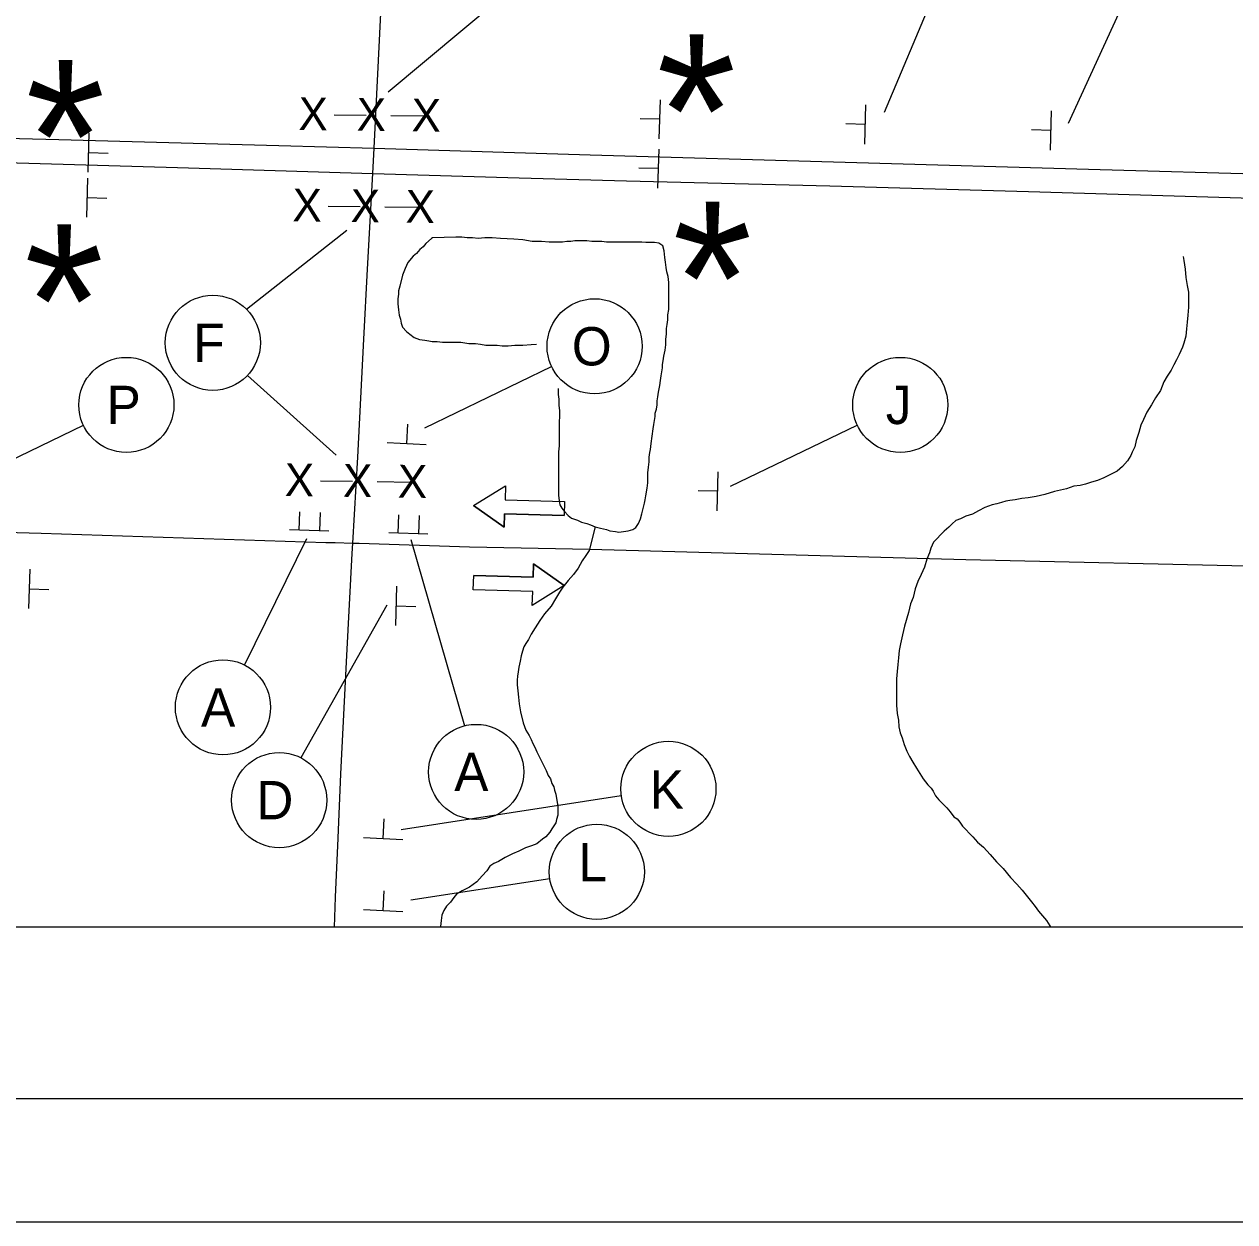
# Model space of a CAD drawing. Extents: x 1 to 1971, y -2 to 1107.
# Drawn here: x 1655.229 to 1660.159, y 1084.601 to 1089.477 of the extents above; entities that cross this region are included whole.
import ezdxf

# ---------------------------------------------------------------- set-up
doc = ezdxf.new("R2010")
doc.units = 0
for name, color, linetype in [('GM_X_County_Road', 7, 'Continuous'), ('GM_X_Minor_River', 7, 'Continuous'), ('GM_X_State_Route', 7, 'Continuous'), ('GM_X_Township_Road', 7, 'Continuous'), ('SH_Border', 7, 'Continuous'), ('SH_Cut_Line', 7, 'Continuous'), ('SH_Data', 7, 'Continuous'), ('SH_Text', 7, 'Continuous'), ('SN_P_Signs', 7, 'Continuous'), ('SN_X_Public', 7, 'Continuous')]:
    doc.layers.add(name, color=color, linetype=linetype)

msp = doc.modelspace()

# ---------------------------------------------------------------- linework, layer by layer
at = {"layer": 'GM_X_County_Road'}
for points in [[(1656.6538, 1088.9713), (1656.6824, 1089.549), (1656.7502, 1090.7723), (1656.779, 1091.2527), (1656.8004, 1091.6678), (1656.8346, 1092.2577), (1656.8383, 1092.3049), (1656.8451, 1092.3768), (1656.8483, 1092.4109)], [(1656.6538, 1088.9713), (1656.6824, 1089.549), (1656.7502, 1090.7723), (1656.779, 1091.2527), (1656.8004, 1091.6678), (1656.8346, 1092.2577), (1656.8383, 1092.3049), (1656.8451, 1092.3768), (1656.8483, 1092.4109)], [(1656.6489, 1088.8688), (1656.6538, 1088.9713)], [(1656.6489, 1088.8688), (1656.6538, 1088.9713)], [(1656.5672, 1087.3642), (1656.5873, 1087.7139), (1656.6125, 1088.1945), (1656.6271, 1088.4787), (1656.6489, 1088.8688)], [(1656.5672, 1087.3642), (1656.5873, 1087.7139), (1656.6125, 1088.1945), (1656.6271, 1088.4787), (1656.6489, 1088.8688)], [(1653.1763, 1087.4595), (1653.5925, 1087.4528), (1654.5111, 1087.4263), (1655.2983, 1087.4042), (1656.4573, 1087.3668), (1656.495, 1087.3659), (1656.5672, 1087.3642)], [(1653.1763, 1087.4595), (1653.5925, 1087.4528), (1654.5111, 1087.4263), (1655.2983, 1087.4042), (1656.4573, 1087.3668), (1656.495, 1087.3659), (1656.5672, 1087.3642)], [(1656.5672, 1087.3642), (1656.5934, 1087.3633), (1657.0425, 1087.3482), (1657.533, 1087.3387), (1659.0643, 1087.2977), (1660.2675, 1087.2696), (1661.405, 1087.2377), (1662.6955, 1087.1976), (1663.5705, 1087.1736), (1663.7236, 1087.1696)], [(1656.5672, 1087.3642), (1656.5934, 1087.3633), (1657.0425, 1087.3482), (1657.533, 1087.3387), (1659.0643, 1087.2977), (1660.2675, 1087.2696), (1661.405, 1087.2377), (1662.6955, 1087.1976), (1663.5705, 1087.1736), (1663.7236, 1087.1696)]]:
    msp.add_lwpolyline(points, dxfattribs=at)
at = {"layer": 'GM_X_Minor_River'}
for points in [[(1656.8922, 1088.6067), (1656.8884, 1088.6046), (1656.8642, 1088.5832), (1656.8535, 1088.5699), (1656.8401, 1088.5592), (1656.8267, 1088.5432), (1656.8133, 1088.5326), (1656.7918, 1088.5059), (1656.7811, 1088.4818), (1656.7757, 1088.4685), (1656.7703, 1088.4551), (1656.7595, 1088.4097), (1656.7541, 1088.391), (1656.7541, 1088.3776), (1656.7513, 1088.3589), (1656.7513, 1088.3375), (1656.7539, 1088.3134), (1656.7565, 1088.292), (1656.7619, 1088.2759), (1656.7645, 1088.2598), (1656.7698, 1088.2437), (1656.7858, 1088.225), (1656.7992, 1088.2142), (1656.8179, 1088.2008), (1656.8393, 1088.1927), (1656.8607, 1088.19), (1656.8767, 1088.1872), (1656.8901, 1088.1845), (1656.9115, 1088.1845), (1656.9329, 1088.1817), (1656.957, 1088.1816), (1656.9811, 1088.1815), (1657.0078, 1088.1815), (1657.0399, 1088.176), (1657.0667, 1088.1759), (1657.0881, 1088.1732), (1657.1095, 1088.1704), (1657.1335, 1088.1704), (1657.155, 1088.1703), (1657.1763, 1088.1675), (1657.2004, 1088.1675), (1657.2272, 1088.1701), (1657.2593, 1088.1699), (1657.2941, 1088.1725), (1657.3151, 1088.174)], [(1657.7071, 1087.4194), (1657.7205, 1087.4274), (1657.7313, 1087.4434), (1657.7393, 1087.4621), (1657.7447, 1087.4835), (1657.7501, 1087.5049), (1657.7555, 1087.5263), (1657.7582, 1087.5396), (1657.7609, 1087.5557), (1657.7664, 1087.5878), (1657.7691, 1087.6092), (1657.7691, 1087.6279), (1657.7692, 1087.6493), (1657.7719, 1087.6734), (1657.7746, 1087.6948), (1657.7747, 1087.7135), (1657.7774, 1087.7322), (1657.7801, 1087.7456), (1657.7828, 1087.7697), (1657.791, 1087.8285), (1657.7937, 1087.8472), (1657.7964, 1087.8632), (1657.7991, 1087.8793), (1657.7992, 1087.8927), (1657.8045, 1087.9087), (1657.8073, 1087.9274), (1657.8073, 1087.9435), (1657.81, 1087.9595), (1657.8127, 1087.9782), (1657.8181, 1088.005), (1657.8209, 1088.0264), (1657.8236, 1088.0451), (1657.8263, 1088.0611), (1657.829, 1088.0772), (1657.8291, 1088.0906), (1657.8318, 1088.1066), (1657.8345, 1088.1253), (1657.8399, 1088.1494), (1657.8426, 1088.1708), (1657.8427, 1088.1922), (1657.8454, 1088.2162), (1657.8454, 1088.2377), (1657.8482, 1088.2537), (1657.8509, 1088.2724), (1657.8509, 1088.2938), (1657.8537, 1088.3152), (1657.8537, 1088.3366), (1657.8537, 1088.3553), (1657.8538, 1088.3741), (1657.8538, 1088.3928), (1657.8539, 1088.4089), (1657.8539, 1088.4249), (1657.8513, 1088.449), (1657.846, 1088.4677), (1657.8433, 1088.4865), (1657.8407, 1088.5079), (1657.8381, 1088.5266), (1657.8355, 1088.5534), (1657.8302, 1088.5748), (1657.8141, 1088.5856), (1657.7954, 1088.5883), (1657.774, 1088.5884), (1657.7606, 1088.5884), (1657.7446, 1088.5885), (1657.7205, 1088.5885), (1657.7044, 1088.5886), (1657.6911, 1088.5886), (1657.675, 1088.5887), (1657.6616, 1088.5887), (1657.6482, 1088.5888), (1657.6322, 1088.5888), (1657.6161, 1088.5889), (1657.6001, 1088.5889), (1657.5813, 1088.5917), (1657.5626, 1088.5917), (1657.5412, 1088.5918), (1657.5198, 1088.5945), (1657.4904, 1088.5946), (1657.4717, 1088.5947), (1657.4556, 1088.5921), (1657.4395, 1088.5921), (1657.4208, 1088.5895), (1657.3967, 1088.5896), (1657.3673, 1088.5897), (1657.3352, 1088.5924), (1657.2977, 1088.5925), (1657.2603, 1088.598), (1657.2228, 1088.6008), (1657.1693, 1088.6037), (1657.1345, 1088.6065), (1657.1051, 1088.6065), (1657.0783, 1088.604), (1657.0543, 1088.6067), (1657.0329, 1088.6068), (1657.0115, 1088.6095), (1656.9874, 1088.6096), (1656.8922, 1088.6067)], [(1659.9493, 1088.5306), (1659.9519, 1088.5145), (1659.9572, 1088.4797), (1659.9598, 1088.4449), (1659.965, 1088.4128), (1659.9703, 1088.3861), (1659.9703, 1088.3566), (1659.9702, 1088.3245), (1659.9675, 1088.2924), (1659.9647, 1088.263), (1659.962, 1088.2363), (1659.9592, 1088.2068), (1659.9511, 1088.1774), (1659.9457, 1088.1614), (1659.9323, 1088.132), (1659.9215, 1088.1106), (1659.9108, 1088.0893), (1659.9, 1088.0679), (1659.8839, 1088.0439), (1659.8705, 1088.0198), (1659.857, 1087.9851), (1659.8356, 1087.9557), (1659.8194, 1087.9264), (1659.8006, 1087.897), (1659.7872, 1087.8676), (1659.7764, 1087.8435), (1659.7683, 1087.8141), (1659.7576, 1087.7821), (1659.7521, 1087.7553), (1659.7414, 1087.734), (1659.736, 1087.7206), (1659.7226, 1087.6993), (1659.7011, 1087.6752), (1659.6797, 1087.6566), (1659.6529, 1087.6433), (1659.6261, 1087.63), (1659.5993, 1087.6194), (1659.5752, 1087.6114), (1659.5511, 1087.6035), (1659.5297, 1087.5982), (1659.5029, 1087.5956), (1659.4735, 1087.585), (1659.4253, 1087.5745), (1659.3851, 1087.5612), (1659.3503, 1087.5533), (1659.3182, 1087.548), (1659.2914, 1087.5455), (1659.2647, 1087.5402), (1659.2433, 1087.5376), (1659.2272, 1087.5349), (1659.2085, 1087.5297), (1659.1897, 1087.5244), (1659.171, 1087.5191), (1659.1415, 1087.5085), (1659.1147, 1087.4952), (1659.0906, 1087.4819), (1659.0638, 1087.4739), (1659.0424, 1087.4633), (1659.0237, 1087.4553), (1659.0076, 1087.442), (1658.9942, 1087.4287), (1658.9754, 1087.4127), (1658.9325, 1087.3673), (1658.9217, 1087.3433), (1658.9163, 1087.3246), (1658.9056, 1087.2979), (1658.8948, 1087.2658), (1658.8813, 1087.2364), (1658.8679, 1087.207), (1658.8571, 1087.1776), (1658.849, 1087.1429), (1658.8383, 1087.1161), (1658.8301, 1087.0814), (1658.814, 1087.0253), (1658.8059, 1086.9905), (1658.7977, 1086.9531), (1658.7923, 1086.9263), (1658.7896, 1086.8969), (1658.7868, 1086.8702), (1658.7841, 1086.8407), (1658.7814, 1086.8113), (1658.7813, 1086.7739), (1658.7812, 1086.7391), (1658.7811, 1086.7043), (1658.7837, 1086.6695), (1658.789, 1086.6427), (1658.7916, 1086.616), (1658.7969, 1086.5919), (1658.8049, 1086.5705), (1658.8129, 1086.5437), (1658.8235, 1086.5169), (1658.8341, 1086.4955), (1658.8475, 1086.4713), (1658.8635, 1086.4472), (1658.8768, 1086.4257), (1658.8901, 1086.4043), (1658.9088, 1086.3802), (1658.9222, 1086.3667), (1658.9302, 1086.3533), (1658.9408, 1086.3346), (1658.9542, 1086.3185)], [(1657.4034, 1087.9934), (1657.4034, 1087.9822), (1657.4033, 1087.9688), (1657.406, 1087.9501), (1657.4059, 1087.926), (1657.4085, 1087.9019), (1657.4085, 1087.8779), (1657.4084, 1087.8591), (1657.4084, 1087.8431), (1657.4083, 1087.8217), (1657.4083, 1087.8029), (1657.4083, 1087.7842), (1657.4082, 1087.7601), (1657.4055, 1087.7361), (1657.4054, 1087.712), (1657.4054, 1087.6879), (1657.4053, 1087.6692), (1657.4053, 1087.6505), (1657.4052, 1087.6291), (1657.4052, 1087.613), (1657.4051, 1087.5969), (1657.4051, 1087.5782), (1657.4051, 1087.5595), (1657.4077, 1087.5354), (1657.4103, 1087.5193), (1657.4183, 1087.5059), (1657.429, 1087.4925), (1657.445, 1087.4764), (1657.4584, 1087.4657), (1657.4824, 1087.4576), (1657.4985, 1087.4495), (1657.5199, 1087.4441), (1657.5359, 1087.4387), (1657.5546, 1087.4306), (1657.576, 1087.4252), (1657.6001, 1087.4197), (1657.6135, 1087.4143), (1657.6375, 1087.4116), (1657.6509, 1087.4089), (1657.6696, 1087.4115), (1657.6884, 1087.4141), (1657.7071, 1087.4194)], [(1657.5546, 1087.4306), (1657.5303, 1087.3344), (1657.5169, 1087.313), (1657.5008, 1087.2916), (1657.4847, 1087.2623), (1657.4659, 1087.2356), (1657.4444, 1087.2116), (1657.4229, 1087.1849), (1657.4095, 1087.1635), (1657.3934, 1087.1368), (1657.3746, 1087.1074), (1657.3478, 1087.0754), (1657.329, 1087.0487), (1657.3102, 1087.0193), (1657.2941, 1086.9926), (1657.2833, 1086.9713), (1657.2726, 1086.9553), (1657.2645, 1086.9419), (1657.2591, 1086.9232), (1657.2537, 1086.9045), (1657.2483, 1086.8831), (1657.2429, 1086.859), (1657.2402, 1086.8403), (1657.2375, 1086.8216), (1657.2374, 1086.8055), (1657.2374, 1086.7868), (1657.24, 1086.7627), (1657.2426, 1086.736), (1657.2453, 1086.7092), (1657.2505, 1086.6771), (1657.2611, 1086.6316), (1657.2718, 1086.6021), (1657.2851, 1086.5807), (1657.2931, 1086.5646), (1657.3011, 1086.5485), (1657.3091, 1086.5324), (1657.3171, 1086.5137), (1657.3277, 1086.4922), (1657.3384, 1086.4708), (1657.3463, 1086.4547), (1657.3543, 1086.4386), (1657.3623, 1086.4172), (1657.373, 1086.4038), (1657.3783, 1086.3851), (1657.3863, 1086.3716), (1657.3889, 1086.3583), (1657.3943, 1086.3422), (1657.4022, 1086.2913), (1657.4021, 1086.2753), (1657.4021, 1086.2565), (1657.3967, 1086.2379), (1657.394, 1086.2245), (1657.3779, 1086.2005), (1657.3698, 1086.1871), (1657.3537, 1086.1684), (1657.3403, 1086.1578), (1657.3162, 1086.1391), (1657.2948, 1086.1312), (1657.2707, 1086.1232), (1657.2439, 1086.1099), (1657.2171, 1086.0993), (1657.1876, 1086.0833), (1657.1608, 1086.0674), (1657.1421, 1086.0594), (1657.126, 1086.0487), (1657.1126, 1086.0301), (1657.0938, 1086.0087), (1657.0723, 1085.9847), (1657.0429, 1085.9634), (1657.0268, 1085.9554), (1657.0134, 1085.9474), (1656.9893, 1085.9341), (1656.9785, 1085.9208), (1656.9651, 1085.9021), (1656.949, 1085.8861), (1656.9383, 1085.8674), (1656.9302, 1085.8487), (1656.9275, 1085.8273), (1656.9248, 1085.8033), (1656.9248, 1085.8005)], [(1658.9542, 1086.3185), (1658.9675, 1086.3051), (1658.9862, 1086.2863), (1658.9995, 1086.2702), (1659.0155, 1086.2487), (1659.0289, 1086.2407), (1659.0396, 1086.2273), (1659.0502, 1086.2112), (1659.0929, 1086.1682), (1659.1116, 1086.1468), (1659.1357, 1086.1253), (1659.1624, 1086.0958), (1659.189, 1086.0663), (1659.2157, 1086.0394), (1659.2451, 1086.0019), (1659.2718, 1085.975), (1659.2931, 1085.9509), (1659.3145, 1085.924), (1659.3305, 1085.9026), (1659.3465, 1085.8838), (1659.3598, 1085.865), (1659.3758, 1085.8463), (1659.3919, 1085.8275), (1659.4052, 1085.806), (1659.41, 1085.8005)]]:
    msp.add_lwpolyline(points, dxfattribs=at)
at = {"layer": 'GM_X_State_Route'}
for points in [[(1653.1763, 1089.0716), (1653.7087, 1089.0563), (1654.4064, 1089.0358), (1654.8887, 1089.0196), (1655.371, 1089.0075), (1656.2656, 1088.9829), (1656.6538, 1088.9713), (1657.5335, 1088.9451), (1659.6102, 1088.8844), (1660.288, 1088.8659), (1660.8126, 1088.8494), (1661.4466, 1088.8312), (1662.4959, 1088.8007), (1663.3048, 1088.777), (1663.7714, 1088.7638), (1663.8294, 1088.7624), (1664.6819, 1088.737), (1665.1629, 1088.7239), (1665.8187, 1088.7038), (1666.2558, 1088.6901), (1667.4561, 1088.6514), (1667.5998, 1088.6492), (1667.8763, 1088.6439)], [(1653.1763, 1089.0716), (1653.7087, 1089.0563), (1654.4064, 1089.0358), (1654.8887, 1089.0196), (1655.371, 1089.0075), (1656.2656, 1088.9829), (1656.6538, 1088.9713), (1657.5335, 1088.9451), (1659.6102, 1088.8844), (1660.288, 1088.8659)], [(1653.1763, 1088.972), (1654.1058, 1088.9448), (1655.1549, 1088.9137), (1655.8542, 1088.8935), (1656.6489, 1088.8688), (1657.2445, 1088.8506), (1657.6825, 1088.8393), (1658.51, 1088.8187), (1659.3192, 1088.7948), (1660.9157, 1088.748), (1661.55, 1088.7295), (1662.0093, 1088.7178), (1663.1466, 1088.6833), (1663.7686, 1088.6652), (1664.4369, 1088.6454), (1665.8366, 1088.6041), (1666.8645, 1088.5732), (1667.7577, 1088.5488), (1667.8763, 1088.5445)], [(1653.1763, 1088.972), (1654.1058, 1088.9448), (1655.1549, 1088.9137), (1655.8542, 1088.8935), (1656.6489, 1088.8688), (1657.2445, 1088.8506), (1657.6825, 1088.8393), (1658.51, 1088.8187), (1659.3192, 1088.7948), (1660.9157, 1088.748), (1661.55, 1088.7295), (1662.0093, 1088.7178), (1663.1466, 1088.6833), (1663.7686, 1088.6652), (1664.4369, 1088.6454), (1665.8366, 1088.6041), (1666.8645, 1088.5732), (1667.7577, 1088.5488), (1668.0608, 1088.5378), (1669.2047, 1088.5077), (1669.5547, 1088.5002), (1670.1889, 1088.4798), (1670.4622, 1088.472)]]:
    msp.add_lwpolyline(points, dxfattribs=at)
at = {"layer": 'GM_X_Township_Road'}
msp.add_lwpolyline([(1656.4923, 1085.8005), (1656.4972, 1085.9224), (1656.5079, 1086.1627), (1656.5193, 1086.425), (1656.5429, 1086.9057), (1656.5646, 1087.3209), (1656.5672, 1087.3642)], dxfattribs=at)
msp.add_lwpolyline([(1656.4923, 1085.8005), (1656.4972, 1085.9224), (1656.5079, 1086.1627), (1656.5193, 1086.425), (1656.5429, 1086.9057), (1656.5646, 1087.3209), (1656.5672, 1087.3642)], dxfattribs=at)
at = {"layer": 'SH_Border'}
msp.add_lwpolyline([(1652.9632, 1106.1005), (1684.9632, 1106.1005), (1684.9632, 1085.1005), (1652.9632, 1085.1005)], close=True, dxfattribs=at)
at = {"layer": 'SH_Cut_Line'}
msp.add_lwpolyline([(1651.4632, 1084.6005), (1685.4632, 1084.6005), (1685.4632, 1106.6005), (1651.4632, 1106.6005)], close=True, dxfattribs=at)
at = {"layer": 'SH_Data'}
msp.add_lwpolyline([(1653.1763, 1105.4005), (1672.2022, 1105.4005), (1672.2022, 1085.8005), (1653.1763, 1085.8005)], close=True, dxfattribs=at)
at = {"layer": 'SH_Text'}
for p, q in [((1656.7115, 1089.2016), (1657.2794, 1089.6766)), ((1658.7325, 1089.1178), (1658.9411, 1089.6146)), ((1659.4825, 1089.0736), (1659.7177, 1089.5889)), ((1656.5437, 1088.6373), (1656.1351, 1088.3156)), ((1656.861, 1087.8338), (1657.3768, 1088.0831)), ((1656.5001, 1087.7221), (1656.1382, 1088.0463)), ((1654.9545, 1087.595), (1655.4702, 1087.8443)), ((1658.1057, 1087.595), (1658.6214, 1087.8443)), ((1657.0592, 1087.5165), (1657.189, 1087.5976)), ((1657.189, 1087.5976), (1657.1874, 1087.5406)), ((1657.1874, 1087.5406), (1657.4293, 1087.5337)), ((1657.4293, 1087.5337), (1657.4277, 1087.4758)), ((1657.0592, 1087.5165), (1657.1842, 1087.4281)), ((1657.1842, 1087.4281), (1657.1858, 1087.4826)), ((1657.1858, 1087.4826), (1657.4277, 1087.4758)), ((1656.3794, 1087.3817), (1656.1263, 1086.8678)), ((1656.8044, 1087.3781), (1657.0222, 1086.62)), ((1657.3031, 1087.2791), (1657.3016, 1087.2245)), ((1657.4282, 1087.1907), (1657.3031, 1087.2791)), ((1657.058, 1087.1734), (1657.0596, 1087.2314)), ((1657.3016, 1087.2245), (1657.0596, 1087.2314)), ((1657.4282, 1087.1907), (1657.2983, 1087.1095)), ((1657.2999, 1087.1665), (1657.058, 1087.1734)), ((1657.2983, 1087.1095), (1657.2999, 1087.1665)), ((1656.7061, 1087.1106), (1656.3553, 1086.49)), ((1656.7648, 1086.1982), (1657.6609, 1086.3361)), ((1656.8032, 1085.9112), (1657.3694, 1085.9983))]:
    msp.add_line(p, q, dxfattribs=at)
for points in [[(1657.4277, 1087.4758), (1657.1858, 1087.4826), (1657.1842, 1087.4281), (1657.0592, 1087.5165), (1657.189, 1087.5976), (1657.1874, 1087.5406), (1657.4293, 1087.5337)], [(1657.0597, 1087.2314), (1657.3016, 1087.2245), (1657.3031, 1087.2791), (1657.4282, 1087.1907), (1657.2983, 1087.1095), (1657.2999, 1087.1665), (1657.058, 1087.1734)]]:
    msp.add_lwpolyline(points, close=True, dxfattribs=at)
msp.add_lwpolyline([(1656.5672, 1087.3642), (1656.5934, 1087.3633), (1657.0425, 1087.3482), (1657.533, 1087.3387), (1659.0643, 1087.2977), (1660.2675, 1087.2696), (1661.405, 1087.2377), (1662.6955, 1087.1976), (1663.5705, 1087.1736), (1663.7236, 1087.1696)], dxfattribs=at)
for centre in [(1655.9975, 1088.1794), (1657.5521, 1088.1653), (1655.6455, 1087.9265), (1658.7967, 1087.9265), (1656.0387, 1086.6951), (1657.0698, 1086.4323), (1657.8526, 1086.3633), (1656.2677, 1086.3173), (1657.5611, 1086.0255)]:
    msp.add_circle(centre, 0.1936, dxfattribs=at)
at = {"layer": 'SN_P_Signs'}
for p, q in [((1656.4922, 1089.1078), (1656.6224, 1089.1061)), ((1658.6523, 1088.9884), (1658.6571, 1089.1483)), ((1659.4084, 1088.9641), (1659.4132, 1089.1241)), ((1656.7225, 1089.1047), (1656.8593, 1089.103)), ((1658.6547, 1089.0684), (1658.5747, 1089.0708)), ((1659.4108, 1089.0441), (1659.3308, 1089.0465)), ((1656.4677, 1088.736), (1656.5978, 1088.7343)), ((1656.6979, 1088.733), (1656.8348, 1088.7312)), ((1656.7869, 1087.7688), (1656.791, 1087.8487)), ((1656.707, 1087.773), (1656.8668, 1087.7647)), ((1658.0508, 1087.4948), (1658.0556, 1087.6547)), ((1656.4362, 1087.6171), (1656.5664, 1087.6154)), ((1656.6665, 1087.6141), (1656.8033, 1087.6123)), ((1658.0532, 1087.5748), (1657.9732, 1087.5771)), ((1656.3487, 1087.4163), (1656.3512, 1087.4916)), ((1656.433, 1087.4136), (1656.4354, 1087.4889)), ((1656.7524, 1087.404), (1656.7548, 1087.4792)), ((1656.8367, 1087.4013), (1656.8391, 1087.4765)), ((1656.4699, 1087.4124), (1656.3103, 1087.4175)), ((1656.8736, 1087.4001), (1656.714, 1087.4052)), ((1655.2522, 1087.2578), (1655.2474, 1087.0979)), ((1656.7459, 1087.188), (1656.7411, 1087.0281)), ((1655.2498, 1087.1779), (1655.3298, 1087.1755)), ((1656.7435, 1087.1081), (1656.8235, 1087.1057)), ((1656.6913, 1086.1609), (1656.6954, 1086.2407)), ((1656.6114, 1086.165), (1656.7712, 1086.1567)), ((1656.6913, 1085.8676), (1656.6954, 1085.9475)), ((1656.6114, 1085.8717), (1656.7712, 1085.8635))]:
    msp.add_line(p, q, dxfattribs=at)
at = {"layer": 'SN_X_Public'}
for p, q in [((1657.8156, 1089.0094), (1657.8203, 1089.1693)), ((1657.818, 1089.0893), (1657.738, 1089.0917)), ((1655.493, 1089.034), (1655.4883, 1088.8741)), ((1657.8098, 1088.8084), (1657.8144, 1088.9684)), ((1655.4906, 1088.9541), (1655.5706, 1088.9517)), ((1657.8121, 1088.8884), (1657.7321, 1088.8907)), ((1655.4876, 1088.8503), (1655.4829, 1088.6904)), ((1655.4853, 1088.7704), (1655.5652, 1088.768))]:
    msp.add_line(p, q, dxfattribs=at)

# ---------------------------------------------------------------- texts
at = {"layer": 'SH_Text'}
for s, height, p in [('*', 0.624, (1657.8038, 1088.8108)), ('*', 0.624, (1655.2344, 1088.7073)), ('*', 0.624, (1657.8692, 1088.1298)), ('*', 0.624, (1655.229, 1088.0372)), ('F', 0.156, (1655.9178, 1088.1014)), ('O', 0.156, (1657.4594, 1088.0873)), ('P', 0.156, (1655.5648, 1087.8485)), ('J', 0.156, (1658.7378, 1087.8485)), ('A', 0.156, (1655.9495, 1086.6171)), ('A', 0.156, (1656.9806, 1086.3543)), ('D', 0.156, (1656.1747, 1086.2393)), ('K', 0.156, (1657.7765, 1086.2822)), ('L', 0.156, (1657.4864, 1085.987))]:
    msp.add_text(s, height=height, dxfattribs=at).set_placement(p)
at = {"layer": 'SN_P_Signs'}
for p in [(1656.3458, 1089.0461), (1656.5827, 1089.043), (1656.8063, 1089.0401), (1656.3212, 1088.6743), (1656.5582, 1088.6712), (1656.7818, 1088.6683), (1656.2898, 1087.5555), (1656.5267, 1087.5524), (1656.7503, 1087.5495)]:
    msp.add_text('X', height=0.1333, rotation=359.2514, dxfattribs=at).set_placement(p)

doc.saveas('drawing.dxf')
